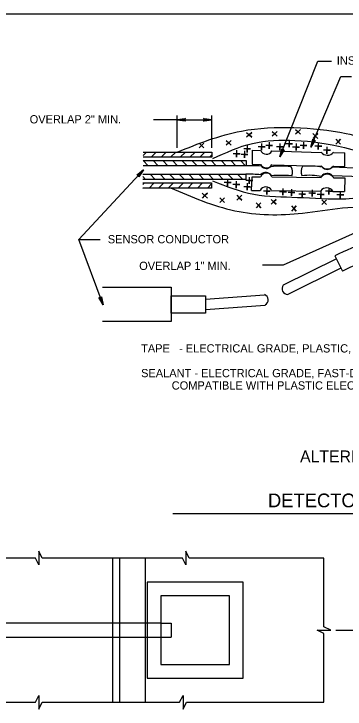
# Model space of a CAD drawing. Extents: x 2709 to 3899, y 22 to 1210.
# Drawn here: x 2982.7 to 3103.3, y 348 to 601.2 of the extents above; entities that cross this region are included whole.
import ezdxf

# ---------------------------------------------------------------- set-up
doc = ezdxf.new("R2010")
doc.units = 0
for name, color, linetype in [('1', 7, 'Continuous'), ('2', 7, 'Continuous'), ('3', 7, 'Continuous')]:
    doc.layers.add(name, color=color, linetype=linetype)

# ---------------------------------------------------------------- blocks, each defined once
blk = doc.blocks.new('RARROW')
at = {"layer": '3'}
blk.add_lwpolyline([(-2.2695, 0.285), (-2.184875, 0.12075), (0, 0), (-2.2695, 0.285), (-2.38575, 0.384625), (0, 0), (-2.183125, -0.108), (-2.262875, -0.2705), (0, 0), (-2.38575, -0.379125), (-2.262875, -0.2705)], dxfattribs=at)

msp = doc.modelspace()

# ---------------------------------------------------------------- linework, layer by layer
at = {"layer": '1'}
for p, q in [((2748.86, 601.17), (3534.86, 601.17)), ((3040.51, 419.23), (3180.88, 419.23))]:
    msp.add_line(p, q, dxfattribs=at)
at = {"layer": '2'}
for p, q in [((3079.5, 549.12), (3093.38, 584)), ((3093.38, 584), (3098.25, 584)), ((3090.75, 552.62), (3101.75, 578.37)), ((3101.75, 578.37), (3105.63, 578.37)), ((3042.13, 562.62), (3033.46, 562.62)), ((3042.13, 552.37), (3042.13, 564.12)), ((3042.13, 562.62), (3054.75, 562.62)), ((3054.75, 552.37), (3054.75, 564.12)), ((3069.38, 551.5), (3072.5, 551.37)), ((3069.38, 551.5), (3069.38, 546.5)), ((3076.63, 551.25), (3094.5, 550.75)), ((3099, 550.75), (3103.13, 550.62)), ((3103.13, 545.62), (3103.13, 550.62)), ((3029.87, 544.36), (3006.38, 519)), ((3069.38, 546.5), (3072.5, 546.37)), ((3076.63, 546.25), (3094.5, 545.75)), ((3110.38, 544.87), (3098.5, 545.37)), ((3099, 545.75), (3103.13, 545.62)), ((3069.13, 536.87), (3069.38, 541.87)), ((3069.38, 541.87), (3072.5, 541.87)), ((3076.63, 541.87), (3094.5, 541.62)), ((3110.38, 541.75), (3098.5, 542.25)), ((3099, 541.5), (3103.13, 541.5)), ((3103.13, 541.5), (3103, 536.5)), ((3069.13, 536.87), (3072.38, 536.87)), ((3076.38, 536.87), (3094.38, 536.62)), ((3098.75, 536.5), (3103, 536.5)), ((3113.68, 524.56), (3080.69, 509.66)), ((3006.38, 519), (3014.13, 519)), ((3015.17, 495.21), (3006.38, 519)), ((3006.38, 519), (3014.13, 519)), ((3100.13, 512), (3080.75, 502.37)), ((3099.5, 513.12), (3102.25, 507.5)), ((3080.69, 509.66), (3073.18, 509.66)), ((3101.75, 508.62), (3082.38, 499)), ((3052.5, 497.25), (3073.88, 498.87)), ((3052.5, 493.5), (3074.13, 495.12)), ((3018.65, 403.01), (3018.65, 350.51)), ((3021.15, 403.01), (3021.15, 350.51)), ((3030.53, 403.01), (3030.53, 350.51)), ((3031.15, 394.26), (3031.15, 359.26)), ((3036.15, 379.26), (3039.9, 379.26)), ((3039.9, 379.26), (3039.9, 374.26)), ((3036.15, 374.26), (3039.9, 374.26))]:
    msp.add_line(p, q, dxfattribs=at)
for points in [[(3067.38, 558), (3068.38, 557.12), (3069.25, 556.25), (3068.38, 557.12), (3069.25, 558), (3068.38, 557.12), (3067.38, 556.25)], [(3076.75, 558.37), (3077.63, 557.5), (3078.5, 556.62), (3077.63, 557.5), (3078.5, 558.37), (3077.63, 557.5), (3076.75, 556.62)], [(3085.25, 559.12), (3086.13, 558.25), (3087, 557.37), (3086.13, 558.25), (3087, 559.12), (3086.13, 558.25), (3085.25, 557.37)], [(3091.5, 557.62), (3092.38, 556.75), (3093.38, 555.75), (3092.38, 556.75), (3093.38, 557.62), (3092.38, 556.75), (3091.5, 555.75)], [(3060, 555.12), (3060.88, 554.25), (3061.75, 553.37), (3060.88, 554.25), (3061.75, 555.12), (3060.88, 554.25), (3060, 553.37)], [(3075.63, 554.5), (3075.63, 553.25), (3075.63, 552), (3075.63, 553.25), (3076.88, 553.25), (3075.63, 553.25), (3074.38, 553.25)], [(3082.84, 555.14), (3082.84, 553.89), (3082.84, 552.64), (3082.84, 553.89), (3084.09, 553.89), (3082.84, 553.89), (3081.59, 553.89)], [(3088.13, 554.5), (3088.13, 553.25), (3088.13, 552), (3088.13, 553.25), (3089.38, 553.25), (3088.13, 553.25), (3086.88, 553.25)], [(3099.88, 555.5), (3100.75, 554.62), (3101.63, 553.75), (3100.75, 554.62), (3101.63, 555.5), (3100.75, 554.62), (3099.88, 553.75)], [(3050.13, 554.12), (3051, 553.25), (3051.88, 552.37), (3051, 553.25), (3051.88, 554.12), (3051, 553.25), (3050.13, 552.37)], [(3067.63, 553.25), (3067.63, 552), (3067.63, 550.75), (3067.63, 552), (3068.88, 552), (3067.63, 552), (3066.38, 552)], [(3072.88, 554), (3072.88, 552.75), (3072.88, 551.5), (3072.88, 552.75), (3074.13, 552.75), (3072.88, 552.75), (3071.63, 552.75)], [(3079.5, 554), (3079.5, 552.75), (3079.5, 551.5), (3079.5, 552.75), (3080.75, 552.75), (3079.5, 552.75), (3078.25, 552.75)], [(3085.39, 553.92), (3085.39, 552.67), (3085.39, 551.42), (3085.39, 552.67), (3086.64, 552.67), (3085.39, 552.67), (3084.14, 552.67)], [(3093.5, 554.26), (3093.5, 553.01), (3093.5, 551.76), (3093.5, 553.01), (3094.75, 553.01), (3093.5, 553.01), (3092.25, 553.01)], [(3096.63, 552.75), (3096.63, 551.5), (3096.63, 550.25), (3096.63, 551.5), (3097.88, 551.5), (3096.63, 551.5), (3095.38, 551.5)], [(3029.75, 549.62), (3031, 550.87)], [(3029.75, 550.87), (3054.75, 550.87), (3054.75, 549), (3029.75, 549), (3029.75, 549)], [(3032.63, 549), (3034.5, 550.87)], [(3036.25, 549), (3038.13, 550.87)], [(3039.75, 549), (3041.63, 550.87)], [(3043.25, 549), (3045.13, 550.87)], [(3046.75, 549), (3048.63, 550.87)], [(3050.38, 549), (3052.25, 550.87)], [(3053.88, 549), (3054.75, 549.87)], [(3063.75, 551.5), (3063.75, 550.25), (3063.75, 549), (3063.75, 550.25), (3065, 550.25), (3063.75, 550.25), (3062.5, 550.25)], [(3066.63, 551.25), (3066.63, 550), (3066.63, 548.75), (3066.63, 550), (3067.88, 550), (3066.63, 550), (3065.38, 550)], [(3031.63, 545.87), (3029.75, 547.75)], [(3029.75, 547.75), (3067.25, 547.75), (3067.25, 545.87), (3029.75, 545.87), (3029.75, 545.87)], [(3035.25, 545.87), (3033.38, 547.75)], [(3038.75, 545.87), (3036.88, 547.75)], [(3042.25, 545.87), (3040.38, 547.75)], [(3045.75, 545.87), (3043.88, 547.75)], [(3049.38, 545.87), (3047.5, 547.75)], [(3052.88, 545.87), (3051, 547.75)], [(3056.38, 545.87), (3054.5, 547.75)], [(3060, 545.87), (3058.13, 547.75)], [(3063.5, 545.87), (3061.63, 547.75)], [(3067, 545.87), (3065.13, 547.75)], [(3029.63, 542.75), (3029.63, 542.75), (3067.13, 542.75), (3067.13, 540.87), (3029.63, 540.87)], [(3030.63, 540.87), (3029.63, 542)], [(3034.13, 540.87), (3032.25, 542.75)], [(3037.75, 540.87), (3035.88, 542.75)], [(3041.25, 540.87), (3039.38, 542.75)], [(3044.75, 540.87), (3042.88, 542.75)], [(3048.25, 540.87), (3046.38, 542.75)], [(3051.88, 540.87), (3050, 542.75)], [(3055.38, 540.87), (3053.5, 542.75)], [(3058.88, 540.87), (3057, 542.75)], [(3062.5, 540.87), (3060.63, 542.75)], [(3066, 540.87), (3064.13, 542.75)], [(3029.63, 539), (3030.25, 539.62)], [(3029.63, 539.62), (3029.63, 539.62), (3054.63, 539.62), (3054.63, 537.75), (3029.63, 537.75)], [(3031.88, 537.75), (3033.75, 539.62)], [(3035.38, 537.75), (3037.25, 539.62)], [(3038.88, 537.75), (3040.75, 539.62)], [(3042.5, 537.75), (3044.38, 539.62)], [(3046, 537.75), (3047.88, 539.62)], [(3049.5, 537.75), (3051.38, 539.62)], [(3053.13, 537.75), (3054.63, 539.25)], [(3060.5, 541), (3060.5, 539.75), (3060.5, 538.5), (3060.5, 539.75), (3061.75, 539.75), (3060.5, 539.75), (3059.25, 539.75)], [(3063.63, 540.25), (3063.63, 539), (3063.63, 537.75), (3063.63, 539), (3064.88, 539), (3063.63, 539), (3062.38, 539)], [(3067.63, 539.5), (3067.63, 538.25), (3067.63, 537), (3067.63, 538.25), (3068.88, 538.25), (3067.63, 538.25), (3066.38, 538.25)], [(3068.38, 541.75), (3068.38, 540.5), (3068.38, 539.25), (3068.38, 540.5), (3069.63, 540.5), (3068.38, 540.5), (3067.13, 540.5)], [(3029.75, 537.75), (3029.63, 537.87)], [(3074.75, 537.87), (3074.75, 536.62), (3074.75, 535.37), (3074.75, 536.62), (3076, 536.62), (3074.75, 536.62), (3073.5, 536.62)], [(3080.63, 537.62), (3080.63, 536.37), (3080.63, 535.12), (3080.63, 536.37), (3081.88, 536.37), (3080.63, 536.37), (3079.38, 536.37)], [(3083.75, 537.37), (3083.75, 536.12), (3083.75, 534.87), (3083.75, 536.12), (3085, 536.12), (3083.75, 536.12), (3082.5, 536.12)], [(3087.63, 536.75), (3087.63, 535.5), (3087.63, 534.25), (3087.63, 535.5), (3088.88, 535.5), (3087.63, 535.5), (3086.38, 535.5)], [(3091.25, 537.12), (3091.25, 535.87), (3091.25, 534.62), (3091.25, 535.87), (3092.5, 535.87), (3091.25, 535.87), (3090, 535.87)], [(3097.38, 537.87), (3097.38, 536.62), (3097.38, 535.37), (3097.38, 536.62), (3098.63, 536.62), (3097.38, 536.62), (3096.13, 536.62)], [(3051.25, 535.87), (3052.13, 535), (3053.13, 534.12), (3052.13, 535), (3053.13, 535.87), (3052.13, 535), (3051.25, 534.12)], [(3057.63, 534.25), (3058.5, 533.37), (3059.38, 532.5), (3058.5, 533.37), (3059.38, 534.25), (3058.5, 533.37), (3057.63, 532.5)], [(3063.88, 535.12), (3064.75, 534.25), (3065.63, 533.37), (3064.75, 534.25), (3065.63, 535.12), (3064.75, 534.25), (3063.88, 533.37)], [(3094.38, 536.62), (3094.38, 535.37), (3094.38, 534.12), (3094.38, 535.37), (3095.63, 535.37), (3094.38, 535.37), (3093.13, 535.37)], [(3101.5, 536.5), (3101.5, 535.25), (3101.5, 534), (3101.5, 535.25), (3102.75, 535.25), (3101.5, 535.25), (3100.25, 535.25)], [(3070.88, 532.37), (3071.75, 531.5), (3072.63, 530.5), (3071.75, 531.5), (3072.63, 532.37), (3071.75, 531.5), (3070.88, 530.5)], [(3076.38, 533.62), (3077.25, 532.75), (3078.13, 531.87), (3077.25, 532.75), (3078.13, 533.62), (3077.25, 532.75), (3076.38, 531.87)], [(3094.75, 533.5), (3095.63, 532.62), (3096.5, 531.75), (3095.63, 532.62), (3096.5, 533.5), (3095.63, 532.62), (3094.75, 531.75)], [(3083.75, 531.25), (3084.63, 530.25), (3085.5, 529.37), (3084.63, 530.25), (3085.5, 531.25), (3084.63, 530.25), (3083.75, 529.37)], [(3015, 501.62), (3015, 501.62), (3040, 501.62), (3040, 489.12), (3015, 489.12)], [(3030.53, 403.01), (2993.03, 403.01), (2991.78, 405.51), (2991.78, 400.51), (2990.53, 403.01), (2940.53, 403.01), (2939.28, 405.51), (2939.28, 400.51), (2938.03, 403.01), (2888.03, 403.01), (2886.78, 405.51), (2886.78, 400.51), (2885.53, 403.01), (2835.53, 403.01), (2834.28, 405.51), (2834.28, 400.51), (2833.03, 403.01), (2795.53, 403.01), (2795.53, 390.51), (2795.53, 378.01), (2798.03, 376.76), (2793.03, 376.76)], [(3046.53, 403.01), (3045.28, 405.51), (3045.28, 400.51), (3044.03, 403.01), (3030.53, 403.01)], [(3098.03, 376.76), (3095.53, 378.01), (3095.53, 403.01), (3046.53, 403.01)], [(3031.15, 359.26), (3066.15, 359.26), (3066.15, 394.26), (3031.15, 394.26), (3031.15, 359.26)], [(3036.15, 364.26), (3061.15, 364.26), (3061.15, 389.26), (3036.15, 389.26), (3036.15, 364.26)], [(3099.9, 376.76), (3108.03, 376.76), (3108.03, 384.26)], [(3036.15, 379.26), (2816.15, 379.26), (2816.15, 374.26), (3036.15, 374.26)], [(2940.53, 350.51), (2990.53, 350.51), (2991.78, 353.01), (2991.78, 348.01), (2993.03, 350.51), (3043.03, 350.51), (3044.28, 353.01), (3044.28, 348.01), (3045.53, 350.51), (3095.53, 350.51), (3095.53, 375.51), (3093.03, 376.76), (3098.03, 376.76)]]:
    msp.add_lwpolyline(points, dxfattribs=at)
msp.add_lwpolyline([(3052.5, 498.5), (3052.5, 492.25), (3040, 492.25), (3040, 498.5)], close=True, dxfattribs=at)
for centre, radius, start, end in [((3074.63, 552.31), 2.25, 202.3058, 332.4878), ((3096.8, 552.47), 2.76, 215.9195, 323.3395), ((3074.63, 547.31), 2.25, 202.3058, 332.4878), ((3074.59, 547.21), 2.34, 217.3499, 319.1787), ((3080.68, 543.63), 3.46, 336.5601, 33.8802), ((3090.68, 543.78), 3.46, 147.6469, 204.967), ((3096.8, 547.47), 2.76, 215.9195, 323.3395), ((3096.74, 546.9), 2.34, 219.0856, 320.9144), ((3074.58, 540.97), 2.25, 25.5122, 155.6942), ((3074.42, 540.83), 2.57, 36.7342, 134.1294), ((3096.74, 540.03), 2.76, 34.6605, 142.0805), ((3096.71, 540.51), 2.57, 44.1349, 141.5301), ((3074.41, 535.97), 2.25, 25.5122, 155.6942), ((3096.56, 535.04), 2.76, 34.6605, 142.0805), ((3082.38, 501.1), 2.07, 141.8585, 271.1691), ((3073.17, 497.01), 2.07, 299.8585, 69.1691)]:
    msp.add_arc(centre, radius, start, end, dxfattribs=at)
for points in [[(3042.13, 550.87), (3065.5, 558.5), (3084.63, 559.75), (3103.63, 557.62), (3124.88, 552), (3141.13, 548.12), (3157.13, 545.5), (3174.88, 540.37)], [(3055.13, 548.5), (3069.5, 554), (3085, 555.12), (3103, 552.5), (3124.13, 545.37)], [(3072.75, 545.75), (3069.88, 545.87), (3067.25, 545.87)], [(3076.38, 545.62), (3079.75, 545.87), (3083.5, 545.62)], [(3094.88, 545.37), (3091.5, 545.75), (3087.75, 545.62)], [(3072.63, 542.62), (3069.75, 542.75), (3067.13, 542.75)], [(3076.5, 542.37), (3079.88, 542.5), (3083.63, 542.37)], [(3094.63, 542), (3091.25, 542.37), (3087.5, 542.25)], [(3055, 540.37), (3070, 535.5), (3085.88, 534.37), (3103.5, 533.87), (3123.63, 537)], [(3039.75, 537.87), (3063.13, 529.5), (3087.75, 528.62), (3102.25, 530.5), (3133.88, 529.12)], [(3121, 521.62), (3111.63, 518.37), (3099.5, 513.12)], [(3123.75, 516.12), (3114.38, 512.87), (3102.25, 507.5)]]:
    msp.add_spline(points, degree=3, dxfattribs=at)

# ---------------------------------------------------------------- block references
for p, xscale, yscale, rotation in [((3042.13, 562.62), 1.2574347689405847, 1.3092961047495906, 180), ((3090.75, 552.62), 1.2574347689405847, 1.3092961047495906, -112.90820489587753), ((3079.5, 549.12), 1.2574347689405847, 1.3092961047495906, -112.234251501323), ((3029.87, 544.36), 1.257434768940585, 1.3092961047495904, 46.9924511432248), ((3015.17, 495.21), 1.2574347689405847, 1.3092961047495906, -69.41384628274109)]:
    msp.add_blockref('RARROW', p, dxfattribs=dict(at, xscale=xscale, yscale=yscale, rotation=rotation))
at = {"layer": '2', "xscale": 1.2574347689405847, "yscale": 1.3092961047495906}
msp.add_blockref('RARROW', (3054.75, 562.62), dxfattribs=at)

# ---------------------------------------------------------------- texts
at = {"layer": '2'}
for s, height, p in [('INSULATED COMPRESSION CONNECTOR', 3, (3100.23, 582.69)), ('OVERLAP 2" MIN.', 3, (2988.44, 561.29)), ('SENSOR CONDUCTOR', 3, (3016.88, 517.62)), ('OVERLAP 1" MIN.', 3, (3028.31, 507.93)), ('TAPE   - ELECTRICAL GRADE, PLASTIC, SELF-ADHESIVE.', 3, (3029, 477.87)), ('SEALANT - ELECTRICAL GRADE, FAST-DRYING, MOISTURE-RESISTANT,', 3, (3029, 468.87)), ('          COMPATIBLE WITH PLASTIC ELECTRICAL TAPE.', 3, (3029, 464.37)), ('ALTERNATE B', 4.3, (3086.86, 437.89)), ('DETECTOR SPLICE', 5, (3075.18, 421.5))]:
    msp.add_text(s, height=height, dxfattribs=at).set_placement(p)

doc.saveas('drawing.dxf')
